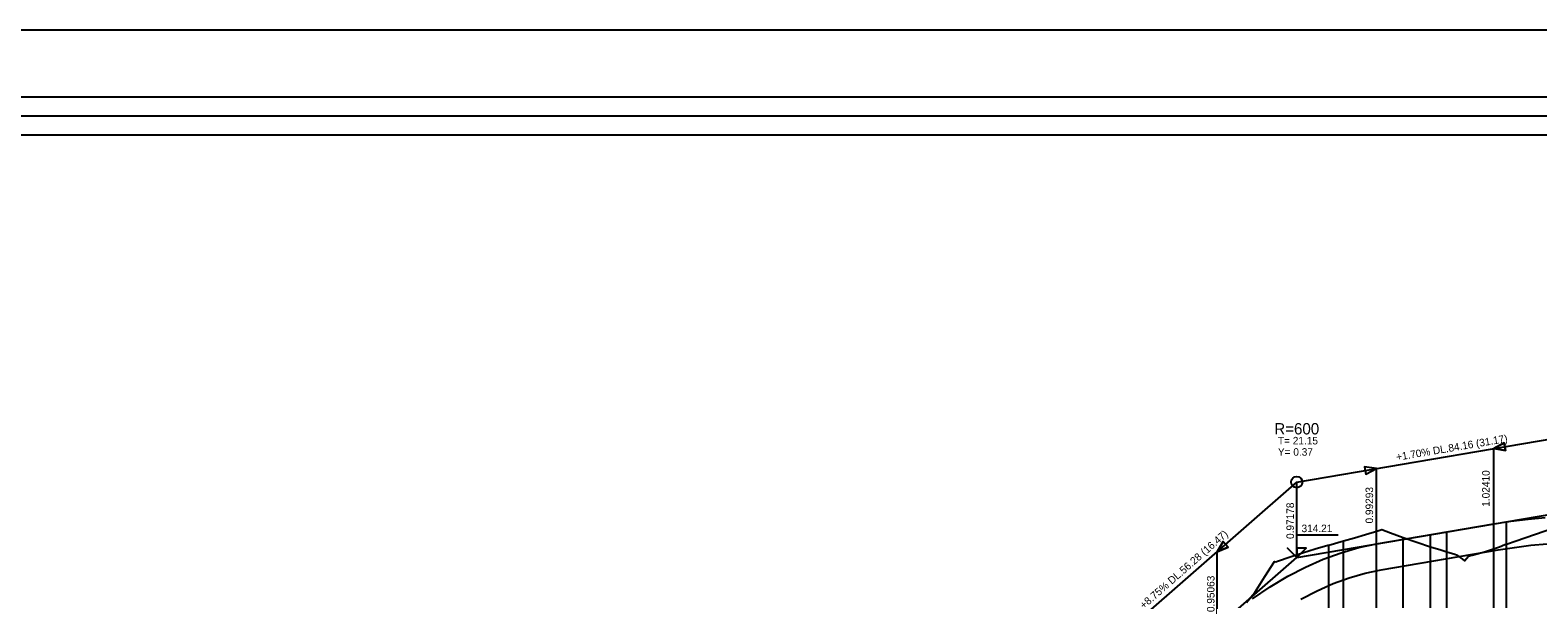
# Model space of a CAD drawing. Extents: x 1301 to 1448, y 183 to 228.
# Drawn here: x 1374.89 to 1414.92, y 212.44 to 227.54 of the extents above; entities that cross this region are included whole.
import ezdxf

# ---------------------------------------------------------------- set-up
doc = ezdxf.new("R2010")
doc.units = 0
for name, color, linetype in [('KOTA', 7, 'Continuous'), ('NOVY_STAV', 7, 'Continuous'), ('NS_OBLOUK', 7, 'Continuous'), ('REZY_PO', 7, 'Continuous'), ('SVK_STAT', 7, 'Continuous'), ('TABULKY', 7, 'Continuous'), ('u_drenaz', 7, 'Continuous'), ('x_formát_rám', 7, 'Continuous')]:
    doc.layers.add(name, color=color, linetype=linetype)

msp = doc.modelspace()

# ---------------------------------------------------------------- linework, layer by layer
at = {"layer": 'KOTA'}
for points in [[(1408.521, 213.539), (1408.271, 213.789), (1408.521, 213.539), (1408.521, 214.139), (1409.621, 214.139)], [(1408.521, 213.789), (1408.521, 213.539), (1408.771, 213.789), (1408.521, 213.789)], [(1408.521, 213.539), (1408.771, 213.789), (1408.521, 213.789)], [(1408.521, 213.539), (1408.521, 213.539)]]:
    msp.add_lwpolyline(points, dxfattribs=at)
at = {"layer": 'NOVY_STAV'}
for points in [[(1408.521, 215.539), (1416.937, 216.971)], [(1402.893, 210.614), (1408.521, 215.539)], [(1408.521, 213.539), (1408.521, 215.539)], [(1371.343, 199.496), (1372.956, 201.369), (1382.912, 202.588), (1387.709, 206.246), (1394.33, 206.448), (1402.893, 208.614), (1408.521, 213.539), (1416.937, 214.971), (1425.443, 212.807)], [(1407.346, 212.437), (1407.816, 212.757), (1408.286, 213.039), (1408.756, 213.285), (1409.226, 213.493), (1409.696, 213.665), (1410.166, 213.801), (1410.635, 213.899), (1413.753, 214.429), (1414.207, 214.5), (1414.662, 214.557), (1415.117, 214.6)]]:
    msp.add_lwpolyline(points, dxfattribs=at)
msp.add_circle((1408.521, 215.539), 0.15, dxfattribs=at)
at = {"layer": 'NS_OBLOUK'}
for points in [[(1413.753, 216.429), (1414.065, 216.381), (1414.031, 216.578), (1413.753, 216.429)], [(1413.753, 214.429), (1413.753, 216.429)], [(1410.357, 215.75), (1410.636, 215.899), (1410.323, 215.947), (1410.357, 215.75)], [(1410.636, 213.899), (1410.636, 215.899)], [(1406.406, 213.688), (1406.697, 213.811), (1406.566, 213.961), (1406.406, 213.688)], [(1406.406, 211.688), (1406.406, 213.688)]]:
    msp.add_lwpolyline(points, dxfattribs=at)
for points in [[(1413.753, 216.429), (1414.031, 216.578), (1414.065, 216.381)], [(1410.636, 215.899), (1410.323, 215.947), (1410.357, 215.75)], [(1406.406, 213.688), (1406.566, 213.961), (1406.697, 213.811)]]:
    msp.add_lwpolyline(points, close=True, dxfattribs=at)
at = {"layer": 'REZY_PO'}
msp.add_lwpolyline([(1407.186, 212.343), (1407.264, 212.441), (1407.343, 212.536), (1407.406, 212.609), (1407.676, 213.035), (1407.928, 213.432), (1407.964, 213.42), (1408.009, 213.437), (1408.343, 213.553), (1408.676, 213.663), (1409.009, 213.766), (1409.343, 213.861), (1409.356, 213.865), (1409.369, 213.868), (1409.764, 213.977), (1409.764, 213.977), (1409.764, 213.977), (1410.054, 214.058), (1410.343, 214.145), (1410.676, 214.248), (1410.779, 214.282), (1411.009, 214.193), (1411.343, 214.07), (1411.343, 214.07), (1411.706, 213.942), (1412.069, 213.824), (1412.069, 213.824), (1412.069, 213.824), (1412.343, 213.737), (1412.509, 213.685), (1412.509, 213.685), (1412.509, 213.685), (1412.717, 213.623), (1412.764, 213.612), (1412.926, 213.495), (1412.974, 213.451), (1413.08, 213.571), (1413.134, 213.587), (1413.183, 213.601), (1413.343, 213.642), (1413.53, 213.696), (1413.718, 213.756), (1413.905, 213.822), (1414.05, 213.879), (1414.092, 213.893), (1414.092, 213.893), (1414.092, 213.893), (1414.343, 213.98), (1415.343, 214.328)], dxfattribs=at)
at = {"layer": 'SVK_STAT'}
for points in [[(1410.636, 194.626), (1410.636, 214.236)], [(1412.509, 194.626), (1412.509, 214.218)], [(1413.753, 194.626), (1413.753, 214.429)], [(1414.092, 194.626), (1414.092, 214.482)], [(1409.369, 194.626), (1409.369, 213.868)], [(1409.764, 194.626), (1409.764, 213.977)], [(1411.343, 194.626), (1411.343, 214.07)], [(1412.069, 194.626), (1412.069, 214.143)]]:
    msp.add_lwpolyline(points, dxfattribs=at)
at = {"layer": 'TABULKY'}
for points in [[(1311.343, 224.76), (1425.461, 224.76), (1425.461, 225.76), (1311.343, 225.76), (1311.343, 224.76)], [(1311.343, 225.26), (1425.461, 225.26)]]:
    msp.add_lwpolyline(points, dxfattribs=at)
at = {"layer": 'u_drenaz'}
msp.add_lwpolyline([(1408.628, 212.428), (1409.06, 212.654), (1409.488, 212.844), (1409.913, 213), (1410.334, 213.121), (1410.766, 213.211), (1413.865, 213.738), (1414.304, 213.807), (1414.739, 213.861), (1415.173, 213.902)], dxfattribs=at)
at = {"layer": 'x_formát_rám'}
msp.add_lwpolyline([(1300.954, 182.987), (1447.954, 182.987), (1447.954, 227.537), (1300.954, 227.537)], close=True, dxfattribs=at)

# ---------------------------------------------------------------- texts
at = {"layer": 'KOTA'}
msp.add_text('314.21', height=0.2, dxfattribs=at).set_placement((1408.648, 214.21))
at = {"layer": 'NOVY_STAV'}
for s, rotation, p in [('+1.70% DL.84.16 (31.17)', 9.657, (1411.179, 216.103)), (' 0.97178', 90, (1408.447, 213.955)), ('+8.75% DL.56.28 (16.47)', 41.1901, (1404.46, 212.16))]:
    msp.add_text(s, height=0.2, rotation=rotation, dxfattribs=at).set_placement(p)
at = {"layer": 'NS_OBLOUK'}
for s, height, p in [('R=600', 0.3, (1407.924, 216.805)), ('T= 21.15', 0.2, (1408.021, 216.539)), ('Y= 0.37', 0.2, (1408.021, 216.239))]:
    msp.add_text(s, height=height, dxfattribs=at).set_placement(p)
for s, p in [(' 1.02410', (1413.643, 214.811)), (' 0.99293', (1410.548, 214.367)), (' 0.95063', (1406.337, 212.014))]:
    msp.add_text(s, height=0.2, rotation=90, dxfattribs=at).set_placement(p)

doc.saveas('drawing.dxf')
